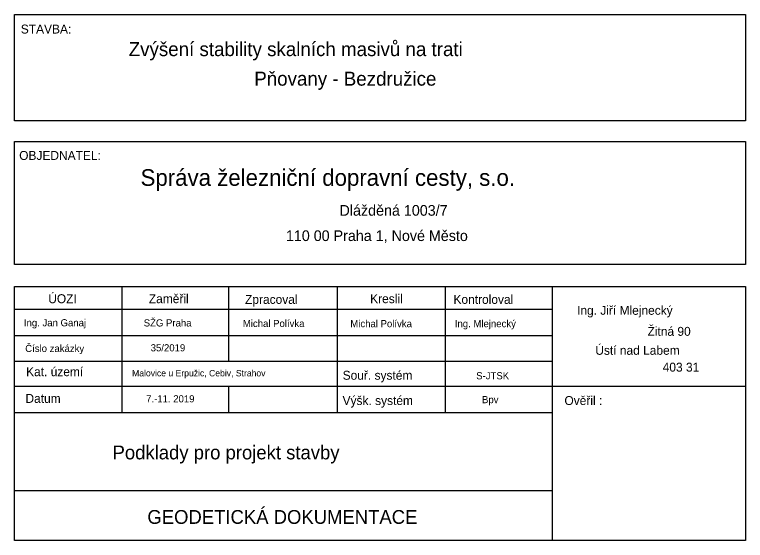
# Model space of a CAD drawing. Extents: x -879530 to -879371, y -1019242 to -1019127.
import ezdxf

# ---------------------------------------------------------------- set-up
doc = ezdxf.new("R2010")
doc.units = 0
doc.layers.add('LEGENDA', color=7, linetype='Continuous')
doc.layers.add('tabulka', color=7, linetype='Continuous')

msp = doc.modelspace()

# ---------------------------------------------------------------- linework, layer by layer
at = {"layer": 'tabulka'}
for p, q in [((-879530.09, -1019186.45), (-879371.44, -1019186.45)), ((-879506.8, -1019186.45), (-879506.8, -1019213.77)), ((-879483.66, -1019186.45), (-879483.66, -1019202.65)), ((-879460.06, -1019186.45), (-879460.06, -1019213.77)), ((-879436.61, -1019186.45), (-879436.61, -1019213.77)), ((-879413.31, -1019241.58), (-879413.31, -1019186.45)), ((-879530.09, -1019191.36), (-879413.31, -1019191.36)), ((-879530.09, -1019197.07), (-879413.31, -1019197.07)), ((-879530.09, -1019202.65), (-879413.31, -1019202.65)), ((-879530.09, -1019208.07), (-879371.44, -1019208.07)), ((-879483.66, -1019208.07), (-879483.66, -1019213.77)), ((-879530.09, -1019213.77), (-879413.31, -1019213.77)), ((-879530.09, -1019230.76), (-879413.31, -1019230.76))]:
    msp.add_line(p, q, dxfattribs=at)
for points in [[(-879530.09, -1019127.36), (-879371.44, -1019127.36), (-879371.44, -1019150.43), (-879530.09, -1019150.43)], [(-879530.09, -1019154.95), (-879371.44, -1019154.95), (-879371.44, -1019181.64), (-879530.09, -1019181.64)]]:
    msp.add_lwpolyline(points, close=True, dxfattribs=at)
msp.add_lwpolyline([(-879371.44, -1019186.45), (-879371.44, -1019241.58), (-879530.09, -1019241.58), (-879530.09, -1019186.45)], dxfattribs=at)

# ---------------------------------------------------------------- texts
at = {"layer": 'LEGENDA'}
for s, p in [('Zvýšení stability skalních masivů na trati', (-879505.32, -1019136.38)), ('Pňovany - Bezdružice', (-879478.06, -1019142.8))]:
    msp.add_text(s, height=3.04, dxfattribs=at).set_placement(p)
at = {"layer": 'tabulka'}
for s, height, p in [('STAVBA:', 1.94, (-879528.75, -1019131.47)), ('OBJEDNATEL:', 1.94, (-879529.1, -1019158.93)), ('Správa železniční dopravní cesty, s.o.', 3.61, (-879502.75, -1019164.56)), ('Dlážděná 1003/7', 2.32, (-879459.55, -1019171.05)), ('110 00 Praha 1, Nové Město', 2.32, (-879471.19, -1019176.55)), ('ÚOZI', 1.94, (-879522.79, -1019190.05)), ('Zaměřil', 1.94, (-879500.95, -1019190.05)), ('Zpracoval', 1.94, (-879480.06, -1019190.2)), ('Kreslil', 1.94, (-879452.9, -1019190.05)), ('Kontroloval', 1.94, (-879434.81, -1019190.2)), ('Ing. Jiří Mlejnecký', 1.94, (-879407.98, -1019192.57)), ('Ing. Jan Ganaj', 1.552, (-879528.08, -1019195.08)), ('SŽG Praha', 1.552, (-879502.06, -1019195.11)), ('Michal Polívka', 1.552, (-879480.54, -1019195.23)), ('Michal Polívka', 1.552, (-879457.21, -1019195.27)), ('Ing. Mlejnecký', 1.552, (-879434.52, -1019195.27)), ('Žitná 90', 1.94, (-879392.68, -1019197.14)), ('Číslo zakázky', 1.552, (-879527.79, -1019200.66)), ('35/2019', 1.552, (-879500.55, -1019200.52)), ('Ústí nad Labem', 1.94, (-879404.02, -1019201.26)), ('403 31', 1.94, (-879389.39, -1019204.92)), ('Kat. území', 1.94, (-879527.6, -1019205.91)), ('Malovice u Erpužic, Cebiv, Strahov', 1.3968, (-879504.59, -1019205.95)), ('Souř. systém', 1.94, (-879458.87, -1019206.68)), ('S-JTSK', 1.552, (-879429.88, -1019206.59)), ('Datum', 1.94, (-879527.74, -1019211.71)), ('7.-11. 2019', 1.552, (-879501.54, -1019211.6)), ('Výšk. systém', 1.94, (-879458.89, -1019212.17)), ('Bpv', 1.552, (-879428.62, -1019211.78)), ('Ověřil :', 1.94, (-879410.72, -1019212.17)), ('Podklady pro projekt stavby', 3, (-879508.83, -1019223.98)), ('GEODETICKÁ DOKUMENTACE ', 3, (-879501.27, -1019237.99))]:
    msp.add_text(s, height=height, dxfattribs=at).set_placement(p)

doc.saveas('drawing.dxf')
